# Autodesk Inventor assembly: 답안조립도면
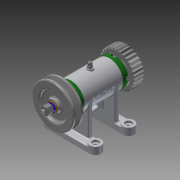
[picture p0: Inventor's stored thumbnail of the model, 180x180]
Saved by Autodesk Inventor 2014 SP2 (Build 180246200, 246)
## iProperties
Created: 2015-11
Part Number: 답안조립도면
Document SubType Name: Assembly
Designer: 702
Author: 702
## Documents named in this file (16)
- C:\Users\702\Desktop\451109V1009\답안조립도면.iam
- C:\Users\702\Desktop\451109V1009\본체.ipt
- C:\Users\702\Desktop\451109V1009\V벨트풀리.ipt
- C:\Users\702\Desktop\451109V1009\너트 M 8.ipt
- C:\Users\702\Desktop\451109V1009\니플 M 6 x 0.75.ipt
- C:\Users\702\Desktop\451109V1009\베어링 15 x 32 x 9.ipt
- C:\Users\702\Desktop\451109V1009\볼트 M 6 x 8.ipt
- C:\Users\702\Desktop\451109V1009\볼트 M4 x 12.ipt
- C:\Users\702\Desktop\451109V1009\스퍼기어.ipt
- C:\Users\702\Desktop\451109V1009\스프링와셔 8.ipt
- C:\Users\702\Desktop\451109V1009\오일 실 15 25 7.ipt
- C:\Users\702\Desktop\451109V1009\와셔 6x11.5.ipt
- C:\Users\702\Desktop\451109V1009\와셔 8x17.ipt
- C:\Users\702\Desktop\451109V1009\축.ipt
- C:\Users\702\Desktop\451109V1009\커버.ipt
- C:\Users\702\Desktop\451109V1009\키 3 x 3 x 12.ipt
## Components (11 placed, 3 different names)
1. V벨트풀리:1
2. KS B 2023 6002 - 15 x 32 x 9:1
3. KS B 2023 6002 - 15 x 32 x 9:2
4. ISO 4762 M4 x 12:2
5. ISO 4762 M4 x 12:3
6. ISO 4762 M4 x 12:4
7. ISO 4762 M4 x 12:5
8. ISO 4762 M4 x 12:1
9. ISO 4762 M4 x 12:6
10. ISO 4762 M4 x 12:7
11. ISO 4762 M4 x 12:8
